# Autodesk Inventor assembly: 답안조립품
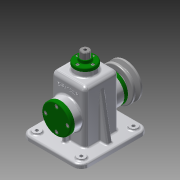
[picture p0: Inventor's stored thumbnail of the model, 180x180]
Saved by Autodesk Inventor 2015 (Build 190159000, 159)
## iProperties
Created: 2016-02
Part Number: 답안조립품
Document SubType Name: Assembly
Designer: Administrator
Author: Administrator
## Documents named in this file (19)
- C:\Users\Administrator\Desktop\460219V1010\답안조립품.iam
- C:\Users\Administrator\Desktop\460219V1010\본체.ipt
- C:\Users\Administrator\Desktop\460219V1010\V-벨트풀리.ipt
- C:\Users\Administrator\Desktop\460219V1010\고정핀.ipt
- C:\Users\Administrator\Desktop\460219V1010\뒤커버.ipt
- C:\Users\Administrator\Desktop\460219V1010\링크.ipt
- C:\Users\Administrator\Desktop\460219V1010\멈춤링 6 x 5.ipt
- C:\Users\Administrator\Desktop\460219V1010\멈춤링 15 x 1.ipt
- C:\Users\Administrator\Desktop\460219V1010\베어링 15 x 35 x 11.ipt
- C:\Users\Administrator\Desktop\460219V1010\볼트 M3 x 8.ipt
- C:\Users\Administrator\Desktop\460219V1010\볼트 M4 x 10.ipt
- C:\Users\Administrator\Desktop\460219V1010\볼트 M6 x 12.ipt
- C:\Users\Administrator\Desktop\460219V1010\상부부시.ipt
- C:\Users\Administrator\Desktop\460219V1010\슬라이드바.ipt
- C:\Users\Administrator\Desktop\460219V1010\앞커버.ipt
- C:\Users\Administrator\Desktop\460219V1010\오일실 15 25 7.ipt
- C:\Users\Administrator\Desktop\460219V1010\와셔.ipt
- C:\Users\Administrator\Desktop\460219V1010\키 5 x 5 x 14.ipt
- C:\Users\Administrator\Desktop\460219V1010\편심축.ipt
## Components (15 placed, 5 different names)
1. V-벨트풀리:1
2. 고정핀:1
3. ISO 4018 M6 x 12:1
4. ISO 4762 M3 x 8:1
5. ISO 4762 M3 x 8:2
6. ISO 4762 M3 x 8:3
7. ISO 4762 M3 x 8:4
8. ISO 4762 M4 x 10:2
9. ISO 4762 M4 x 10:3
10. ISO 4762 M4 x 10:4
11. ISO 4762 M4 x 10:5
12. ISO 4762 M4 x 10:1
13. ISO 4762 M4 x 10:6
14. ISO 4762 M4 x 10:7
15. ISO 4762 M4 x 10:8
